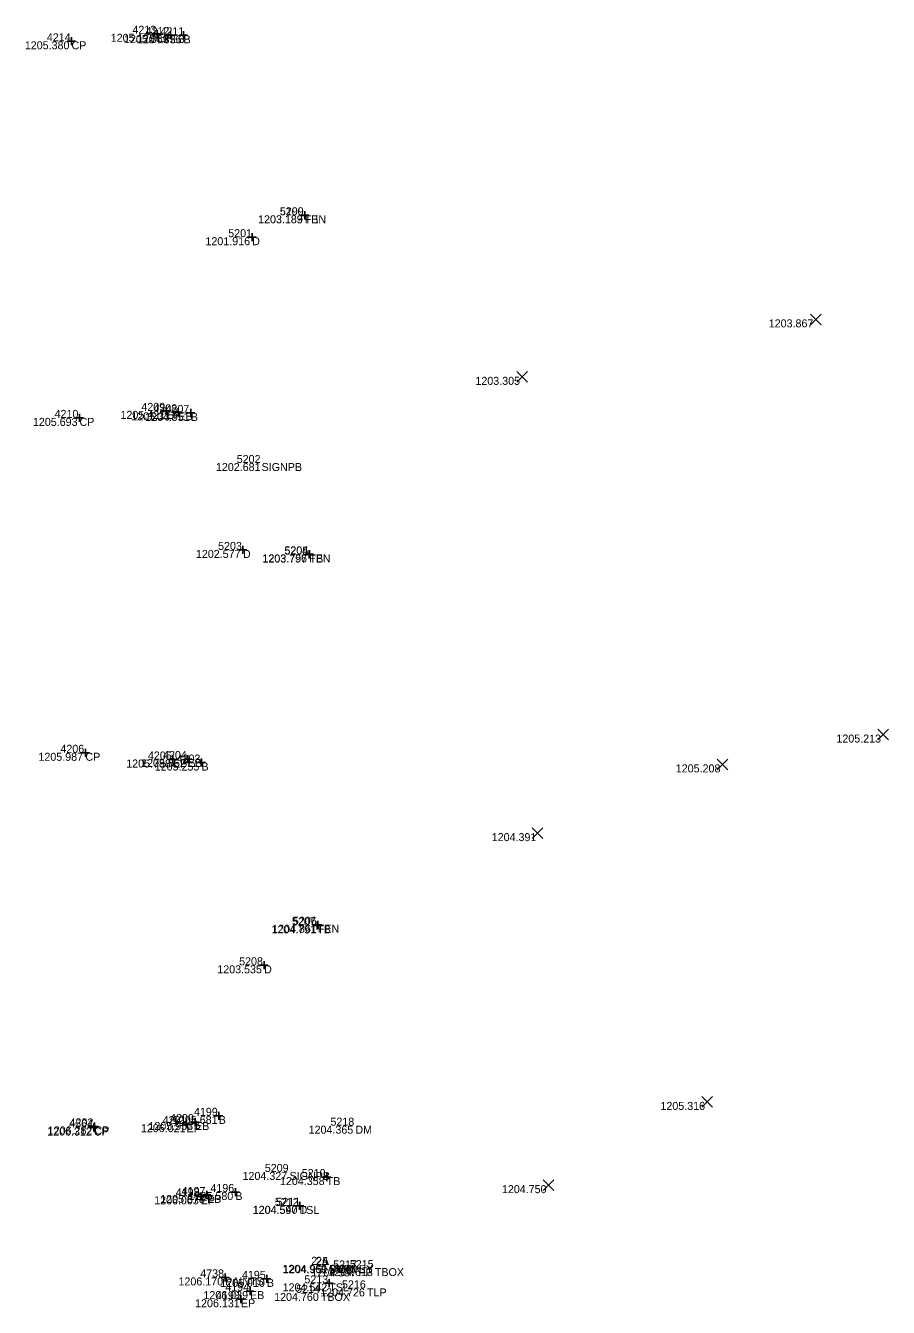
# Model space of a CAD drawing. Extents: x 2044997 to 2050342, y 455233 to 458054.
# Drawn here: x 2047623.3 to 2047731.2, y 457010.4 to 457170.6 of the extents above; entities that cross this region are included whole.
import ezdxf

# ---------------------------------------------------------------- set-up
doc = ezdxf.new("R2010")
doc.units = 0
for name, color, linetype in [('SV_X_Random_Point', 7, 'Continuous'), ('SV_X_Shot_Marker', 7, 'Continuous'), ('SV_X_Text_Comment', 7, 'Continuous'), ('SV_X_Text_Elevation', 7, 'Continuous'), ('SV_X_Text_Name', 7, 'Continuous')]:
    doc.layers.add(name, color=color, linetype=linetype)

msp = doc.modelspace()

# ---------------------------------------------------------------- linework, layer by layer
at = {"layer": 'SV_X_Random_Point'}
for p, q in [((2047721.45, 457133.23), (2047722.78, 457134.57)), ((2047721.45, 457134.57), (2047722.78, 457133.23)), ((2047684.75, 457126.06), (2047686.08, 457127.39)), ((2047684.75, 457127.39), (2047686.08, 457126.06)), ((2047729.86, 457081.35), (2047731.19, 457082.69)), ((2047729.86, 457082.69), (2047731.19, 457081.35)), ((2047709.79, 457077.62), (2047711.12, 457078.96)), ((2047709.79, 457078.96), (2047711.12, 457077.62)), ((2047686.66, 457069.03), (2047688, 457070.36)), ((2047686.66, 457070.36), (2047688, 457069.03)), ((2047707.88, 457035.45), (2047709.21, 457036.78)), ((2047707.88, 457036.78), (2047709.21, 457035.45)), ((2047688.05, 457025.05), (2047689.39, 457026.38)), ((2047688.05, 457026.38), (2047689.39, 457025.05))]:
    msp.add_line(p, q, dxfattribs=at)
at = {"layer": 'SV_X_Shot_Marker'}
for p, q in [((2047639.79, 457170.09), (2047639.79, 457169.09)), ((2047641.46, 457169.93), (2047641.46, 457168.93)), ((2047643.09, 457169.9), (2047643.09, 457168.9)), ((2047628.58, 457168.65), (2047629.58, 457168.65)), ((2047629.08, 457169.15), (2047629.08, 457168.15)), ((2047629.08, 457168.65), (2047629.08, 457168.65)), ((2047639.29, 457169.59), (2047640.29, 457169.59)), ((2047639.79, 457169.59), (2047639.79, 457169.59)), ((2047640.96, 457169.43), (2047641.96, 457169.43)), ((2047641.46, 457169.43), (2047641.46, 457169.43)), ((2047642.59, 457169.4), (2047643.59, 457169.4)), ((2047643.09, 457169.4), (2047643.09, 457169.4)), ((2047658.23, 457147.41), (2047658.23, 457146.41)), ((2047658.23, 457147.4), (2047658.23, 457146.4)), ((2047657.73, 457146.91), (2047658.73, 457146.91)), ((2047657.73, 457146.9), (2047658.73, 457146.9)), ((2047658.23, 457146.91), (2047658.23, 457146.91)), ((2047658.23, 457146.9), (2047658.23, 457146.9)), ((2047651.67, 457144.67), (2047651.67, 457143.67)), ((2047651.17, 457144.17), (2047652.17, 457144.17)), ((2047651.67, 457144.17), (2047651.67, 457144.17)), ((2047630.08, 457122.09), (2047630.08, 457121.09)), ((2047640.41, 457122.47), (2047641.41, 457122.47)), ((2047640.91, 457122.97), (2047640.91, 457121.97)), ((2047640.91, 457122.47), (2047640.91, 457122.47)), ((2047641.93, 457122.29), (2047642.93, 457122.29)), ((2047642.43, 457122.79), (2047642.43, 457121.79)), ((2047642.43, 457122.29), (2047642.43, 457122.29)), ((2047643.49, 457122.21), (2047644.49, 457122.21)), ((2047643.99, 457122.71), (2047643.99, 457121.71)), ((2047643.99, 457122.21), (2047643.99, 457122.21)), ((2047629.58, 457121.59), (2047630.58, 457121.59)), ((2047630.08, 457121.59), (2047630.08, 457121.59)), ((2047650.01, 457105.09), (2047651.01, 457105.09)), ((2047650.51, 457105.59), (2047650.51, 457104.59)), ((2047650.51, 457105.09), (2047650.51, 457105.09)), ((2047658.28, 457104.54), (2047659.28, 457104.54)), ((2047658.33, 457104.5), (2047659.33, 457104.5)), ((2047658.78, 457105.04), (2047658.78, 457104.04)), ((2047658.78, 457104.54), (2047658.78, 457104.54)), ((2047658.83, 457105), (2047658.83, 457104)), ((2047658.83, 457104.5), (2047658.83, 457104.5)), ((2047630.82, 457080.24), (2047630.82, 457079.24)), ((2047630.32, 457079.74), (2047631.32, 457079.74)), ((2047630.82, 457079.74), (2047630.82, 457079.74)), ((2047641.26, 457078.9), (2047642.26, 457078.9)), ((2047641.76, 457079.4), (2047641.76, 457078.4)), ((2047641.76, 457078.9), (2047641.76, 457078.9)), ((2047643.11, 457078.96), (2047644.11, 457078.96)), ((2047643.61, 457079.46), (2047643.61, 457078.46)), ((2047643.61, 457078.96), (2047643.61, 457078.96)), ((2047644.82, 457078.52), (2047645.82, 457078.52)), ((2047645.32, 457079.02), (2047645.32, 457078.02)), ((2047645.32, 457078.52), (2047645.32, 457078.52)), ((2047659.29, 457058.16), (2047660.29, 457058.16)), ((2047659.37, 457058.25), (2047660.37, 457058.25)), ((2047659.79, 457058.66), (2047659.79, 457057.66)), ((2047659.79, 457058.16), (2047659.79, 457058.16)), ((2047659.87, 457058.75), (2047659.87, 457057.75)), ((2047659.87, 457058.25), (2047659.87, 457058.25)), ((2047652.65, 457053.18), (2047653.65, 457053.18)), ((2047653.15, 457053.68), (2047653.15, 457052.68)), ((2047653.15, 457053.18), (2047653.15, 457053.18)), ((2047643.46, 457033.83), (2047643.46, 457032.83)), ((2047644.52, 457034.1), (2047644.52, 457033.1)), ((2047646.98, 457034.37), (2047647.98, 457034.37)), ((2047647.48, 457034.87), (2047647.48, 457033.87)), ((2047647.48, 457034.37), (2047647.48, 457034.37)), ((2047631.37, 457032.91), (2047632.37, 457032.91)), ((2047631.45, 457033.05), (2047632.45, 457033.05)), ((2047631.87, 457033.41), (2047631.87, 457032.41)), ((2047631.87, 457032.91), (2047631.87, 457032.91)), ((2047631.95, 457033.55), (2047631.95, 457032.55)), ((2047631.95, 457033.05), (2047631.95, 457033.05)), ((2047642.96, 457033.33), (2047643.96, 457033.33)), ((2047643.46, 457033.33), (2047643.46, 457033.33)), ((2047644.02, 457033.6), (2047645.02, 457033.6)), ((2047644.52, 457033.6), (2047644.52, 457033.6)), ((2047660.48, 457026.72), (2047661.48, 457026.72)), ((2047660.98, 457027.22), (2047660.98, 457026.22)), ((2047660.98, 457026.72), (2047660.98, 457026.72)), ((2047644.73, 457024.31), (2047645.73, 457024.31)), ((2047645.23, 457024.81), (2047645.23, 457023.81)), ((2047645.23, 457024.31), (2047645.23, 457024.31)), ((2047645.51, 457024.48), (2047646.51, 457024.48)), ((2047646.01, 457024.98), (2047646.01, 457023.98)), ((2047646.01, 457024.48), (2047646.01, 457024.48)), ((2047649.06, 457024.85), (2047650.06, 457024.85)), ((2047649.56, 457025.35), (2047649.56, 457024.35)), ((2047649.56, 457024.85), (2047649.56, 457024.85)), ((2047657.09, 457023.13), (2047658.09, 457023.13)), ((2047657.1, 457023.11), (2047658.1, 457023.11)), ((2047657.59, 457023.63), (2047657.59, 457022.63)), ((2047657.59, 457023.13), (2047657.59, 457023.13)), ((2047657.6, 457023.61), (2047657.6, 457022.61)), ((2047657.6, 457023.11), (2047657.6, 457023.11)), ((2047648.28, 457014.68), (2047648.28, 457013.68)), ((2047653.5, 457014.5), (2047653.5, 457013.5)), ((2047647.78, 457014.18), (2047648.78, 457014.18)), ((2047648.28, 457014.18), (2047648.28, 457014.18)), ((2047651.39, 457012.97), (2047651.39, 457011.97)), ((2047653, 457014), (2047654, 457014)), ((2047653.5, 457014), (2047653.5, 457014)), ((2047660.8, 457013.44), (2047661.8, 457013.44)), ((2047661.3, 457013.94), (2047661.3, 457012.94)), ((2047661.3, 457013.44), (2047661.3, 457013.44)), ((2047649.75, 457011.45), (2047650.75, 457011.45)), ((2047650.25, 457011.95), (2047650.25, 457010.95)), ((2047650.25, 457011.45), (2047650.25, 457011.45)), ((2047650.89, 457012.47), (2047651.89, 457012.47)), ((2047651.39, 457012.47), (2047651.39, 457012.47))]:
    msp.add_line(p, q, dxfattribs=at)

# ---------------------------------------------------------------- texts
at = {"layer": 'SV_X_Text_Comment'}
for s, p in [('CP', (2047629.08, 457167.65)), ('EP', (2047639.79, 457168.59)), ('EB', (2047641.46, 457168.43)), ('B', (2047643.09, 457168.4)), ('TB', (2047658.23, 457145.9)), ('FEN', (2047658.23, 457145.91)), ('D', (2047651.67, 457143.17)), ('EP', (2047640.91, 457121.47)), ('EB', (2047642.43, 457121.29)), ('B', (2047643.99, 457121.21)), ('CP', (2047630.08, 457120.59)), ('SIGNPB', (2047652.84, 457114.95)), ('D', (2047650.51, 457104.09)), ('TB', (2047658.83, 457103.5)), ('FEN', (2047658.78, 457103.54)), ('CP', (2047630.82, 457078.74)), ('EP', (2047641.76, 457077.9)), ('EB', (2047643.61, 457077.96)), ('B', (2047645.32, 457077.52)), ('TB', (2047659.79, 457057.16)), ('FEN', (2047659.87, 457057.25)), ('D', (2047653.15, 457052.18)), ('B', (2047647.48, 457033.37)), ('CP', (2047631.87, 457031.91)), ('CP', (2047631.95, 457032.05)), ('EP', (2047643.46, 457032.33)), ('EB', (2047644.52, 457032.6)), ('DM', (2047664.56, 457032.14)), ('SIGNPB', (2047656.34, 457026.36)), ('TB', (2047660.98, 457025.72)), ('EP', (2047645.23, 457023.31)), ('EB', (2047646.01, 457023.48)), ('B', (2047649.56, 457023.85)), ('TSL', (2047657.6, 457022.11)), ('D', (2047657.59, 457022.13)), ('CMON', (2047661.23, 457014.7)), ('SURVEY', (2047661.27, 457014.75)), ('MON', (2047661.27, 457014.75)), ('PP', (2047664.95, 457014.3)), ('TBOX', (2047667, 457014.35)), ('PAINTS', (2047648.28, 457013.18)), ('B', (2047653.5, 457013)), ('TSL', (2047661.3, 457012.44)), ('EP', (2047650.25, 457010.45)), ('EB', (2047651.39, 457011.47)), ('TBOX', (2047660.24, 457011.24)), ('TLP', (2047666.01, 457011.81))]:
    msp.add_text(s, height=1, dxfattribs=at).set_placement(p)
at = {"layer": 'SV_X_Text_Elevation'}
for s, p in [('1205.380', (2047623.24, 457167.65)), ('1205.179', (2047633.98, 457168.59)), ('1205.069', (2047635.64, 457168.43)), ('1204.836', (2047637.25, 457168.4)), ('1203.183', (2047652.4, 457145.91)), ('1203.189', (2047652.41, 457145.9)), ('1201.916', (2047645.82, 457143.17)), ('1203.867', (2047716.24, 457132.9)), ('1203.305', (2047679.57, 457125.72)), ('1205.421', (2047635.2, 457121.47)), ('1205.337', (2047636.55, 457121.29)), ('1204.951', (2047638.27, 457121.21)), ('1205.693', (2047624.25, 457120.59)), ('1202.681', (2047647.13, 457114.95)), ('1202.577', (2047644.63, 457104.09)), ('1203.756', (2047652.94, 457103.54)), ('1203.797', (2047652.95, 457103.5)), ('1205.213', (2047724.7, 457081.02)), ('1205.987', (2047624.94, 457078.74)), ('1205.788', (2047635.92, 457077.9)), ('1205.562', (2047637.78, 457077.96)), ('1205.255', (2047639.48, 457077.52)), ('1205.208', (2047704.62, 457077.29)), ('1204.391', (2047681.61, 457068.7)), ('1204.791', (2047654.07, 457057.16)), ('1204.861', (2047654.16, 457057.25)), ('1203.535', (2047647.3, 457052.18)), ('1205.316', (2047702.7, 457035.11)), ('1205.681', (2047641.76, 457033.37)), ('1206.312', (2047626.04, 457031.91)), ('1206.282', (2047626.11, 457032.05)), ('1206.021', (2047637.75, 457032.33)), ('1205.953', (2047638.69, 457032.6)), ('1204.365', (2047658.72, 457032.14)), ('1204.327', (2047650.46, 457026.36)), ('1204.358', (2047655.14, 457025.72)), ('1204.750', (2047682.88, 457024.71)), ('1206.003', (2047639.41, 457023.31)), ('1205.878', (2047640.17, 457023.48)), ('1205.580', (2047643.72, 457023.85)), ('1204.597', (2047651.72, 457022.11)), ('1204.540', (2047651.75, 457022.13)), ('1204.969', (2047655.45, 457014.75)), ('1204.969', (2047655.45, 457014.75)), ('1204.951', (2047655.52, 457014.7)), ('1204.557', (2047659.07, 457014.3)), ('1204.613', (2047661.17, 457014.35)), ('1206.170', (2047642.45, 457013.18)), ('1205.910', (2047647.67, 457013)), ('1204.542', (2047655.47, 457012.44)), ('1206.131', (2047644.53, 457010.45)), ('1206.039', (2047645.57, 457011.47)), ('1204.760', (2047654.41, 457011.24)), ('1204.726', (2047660.17, 457011.81))]:
    msp.add_text(s, height=1, dxfattribs=at).set_placement(p)
at = {"layer": 'SV_X_Text_Name'}
for s, p in [('4213', (2047636.69, 457169.59)), ('4212', (2047638.34, 457169.43)), ('4211', (2047640.2, 457169.4)), ('4214', (2047625.99, 457168.65)), ('5200', (2047655.11, 457146.91)), ('5199', (2047655.13, 457146.9)), ('5201', (2047648.67, 457144.17)), ('4209', (2047637.81, 457122.47)), ('4210', (2047626.96, 457121.59)), ('4208', (2047639.31, 457122.29)), ('4207', (2047640.83, 457122.21)), ('5202', (2047649.73, 457115.95)), ('5203', (2047647.4, 457105.09)), ('5204', (2047655.69, 457104.54)), ('5205', (2047655.7, 457104.5)), ('4206', (2047627.69, 457079.74)), ('4205', (2047638.63, 457078.9)), ('4204', (2047640.52, 457078.96)), ('4203', (2047642.21, 457078.52)), ('5207', (2047656.63, 457058.16)), ('5206', (2047656.75, 457058.25)), ('5208', (2047650.03, 457053.18)), ('4199', (2047644.38, 457034.37)), ('4564', (2047628.78, 457032.91)), ('4202', (2047628.83, 457033.05)), ('4201', (2047640.46, 457033.33)), ('4200', (2047641.4, 457033.6)), ('5218', (2047661.45, 457033.14)), ('5209', (2047653.24, 457027.36)), ('5210', (2047657.86, 457026.72)), ('4196', (2047646.44, 457024.85)), ('4198', (2047642.11, 457024.31)), ('4197', (2047642.85, 457024.48)), ('5212', (2047654.49, 457023.11)), ('5211', (2047654.69, 457023.13)), ('2_1', (2047659.05, 457015.75)), ('2A', (2047659.63, 457015.75)), ('25', (2047659.66, 457015.7)), ('5217', (2047661.79, 457015.3)), ('5215', (2047663.87, 457015.35)), ('4738', (2047645.17, 457014.18)), ('4195', (2047650.38, 457014)), ('5213', (2047658.19, 457013.44)), ('4194', (2047648.3, 457012.47)), ('5214', (2047657.15, 457012.24)), ('5216', (2047662.89, 457012.81)), ('4193', (2047647.14, 457011.45))]:
    msp.add_text(s, height=1, dxfattribs=at).set_placement(p)

doc.saveas('drawing.dxf')
